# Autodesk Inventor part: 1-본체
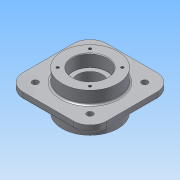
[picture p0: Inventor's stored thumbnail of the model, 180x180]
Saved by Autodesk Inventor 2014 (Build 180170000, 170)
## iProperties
Created: 2015-09
Part Number: 1-본체
Material: 알루미늄 6061
Document SubType Name: Modeling
Designer: study
Density: 2.71 g/cm^3
Appearance: 알루미늄 - 평지
Mass: 1464.68 g
Surface Area: 800.934 cm^2
Volume: 540.471 cm^3
Author: study
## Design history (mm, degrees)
sketch "스케치1"
  geometry: L1 (-75, 75)-(75, 75); L2 (75, 75)-(75, -75); L3 (75, -75)-(-75, -75); L4 (-75, -75)-(-75, 75); L5 (-75, 75)-(75, -75); L6 (75, 75)-(-75, -75); 1 further point
  constraints: 12 end point, 2 midpoint, 2 parallel, 1 horizontal, 1 perpendicular
  dimensions: "d0" = 150 distance of L1.start L1.end; "d1" = 150 distance of L3.end L1.start
extrude "돌출1" new body sketch "스케치1" distance "d2" = 12; taper "d3" = 0 deg
sketch "스케치2"
  geometry: C1 r 50 at (0, 0); 1 further point
  constraints: 1 centre point, 1 coincident
  dimensions: "d5" = 100 diameter of C1
extrude "돌출2" join sketch "스케치2" distance "d6" = 23; taper "d7" = 0 deg
sketch "스케치3"
  geometry: C1 r 50 at (0, 0); 1 further point
  constraints: 1 centre point, 1 coincident
  dimensions: "d8" = 100 diameter of C1
extrude "돌출3" join sketch "스케치3" distance "d9" = 35; taper "d10" = 0 deg
sketch "스케치4"
  geometry: C1 r 50 at (0, 0) reference
hole "구멍1" sketch "스케치4" at (0, 0) diameter "d16" = 45; stored, may be unused: countersink angle "d20" = 90 deg, drill point angle "d22" = 118 deg; dims "d17" = 6, "d18" = 62, "d19" = 22, "d21" = 8
hole "구멍2" diameter "d25" = 45; stored, may be unused: countersink angle "d29" = 90 deg, drill point angle "d31" = 118 deg; dims "d23" = 10, "d24" = 10, "d26" = 6, "d27" = 62, "d28" = 22, "d30" = 8
sketch "스케치7"
  geometry: C1 r 31 at (0, 0) reference; C2 r 50 at (0, 0) reference; A1 r 41 centre (0, 0) between (-28.991, 28.991) and (28.991, 28.991); 2 further points
  constraints: 4 point on circle, 2 vertical alignment, 1 centre point, 1 coincident, 1 horizontal alignment
  dimensions: "d51" = 82 diameter of A1; "d53" = 90 deg dimension on C1.centre A1.start A1.end
hole "구멍5" sketch "스케치7" at (-28.991, 28.991), (28.991, 28.991), (-28.991, -28.991), (28.991, -28.991) diameter "d54" = 4.917; stored, may be unused: countersink angle "d58" = 90 deg, drill point angle "d60" = 118 deg; dims "d55" = 10, "d56" = 62, "d57" = 22, "d59" = 13
sketch "스케치9"
  geometry: C1 r 50 at (0, 0) reference; C2 r 10 at (-49, 49); C3 r 10 at (49, 49); C4 r 10 at (-49, -49); C5 r 10 at (49, -49)
  constraints: 4 centre point, 2 horizontal alignment, 1 equal radius
  dimensions: "d62" = 20 diameter of C2; "d63" = 49 horizontal distance of C1.centre C2.centre; "d64" = 98 distance of C3.centre C2.centre; "d65" = 20 diameter of C5; "d66" = 20 diameter of C4; "d67" = 49 horizontal distance of C1.centre C4.centre; "d68" = 98 distance of C5.centre C4.centre; "d69" = 49 horizontal distance of C1.centre C2.centre; "d70" = 98 distance of C4.centre C2.centre
extrude "돌출5" join sketch "스케치9" distance "d71" = 5; taper "d72" = 0 deg
sketch "스케치10"
  geometry: C1 r 10 at (0, 0) reference; 1 further point
sketch "스케치11"
  geometry: L1 (75, 75)-(-75, 75) reference; L2 (-75, 75)-(-75, -75) reference; L3 (-75, -75)-(75, -75) reference; L4 (75, -75)-(75, 75) reference; C1 r 10 at (-49, -49) reference; C2 r 10 at (-49, 49) reference; C3 r 10 at (49, 49) reference; C4 r 10 at (49, -49) reference; C5 r 50 at (0, 0) reference
hole "구멍7" sketch "스케치10" diameter "d80" = 11; stored, may be unused: countersink angle "d84" = 90 deg, drill point angle "d86" = 0 deg; dims "d81" = 10, "d82" = 62, "d83" = 22, "d85" = 13
sketch "스케치12"
  geometry: C1 r 10 at (0, 0) reference; 1 further point
hole "구멍8" sketch "스케치12" at (0, 0) diameter "d87" = 11; stored, may be unused: countersink angle "d91" = 90 deg, drill point angle "d93" = 0 deg; dims "d88" = 10, "d89" = 62, "d90" = 22, "d92" = 13
sketch "스케치13"
  geometry: C1 r 10 at (0, 0) reference; 1 further point
hole "구멍9" sketch "스케치13" at (0, 0) diameter "d94" = 11; stored, may be unused: countersink angle "d98" = 90 deg, drill point angle "d100" = 0 deg; dims "d95" = 10, "d96" = 62, "d97" = 22, "d99" = 13
sketch "스케치14"
  geometry: C1 r 10 at (0, 0) reference; 1 further point
hole "구멍10" sketch "스케치14" at (0, 0) diameter "d101" = 11; stored, may be unused: countersink angle "d105" = 90 deg, drill point angle "d107" = 0 deg; dims "d102" = 10, "d103" = 62, "d104" = 22, "d106" = 13
fillet "모깎기2" dims "d108" = 30
fillet "모깎기3" dims "d109" = 3, "d110" = 0.3
chamfer "모따기1" distance "d111" = 1; stored, may be unused: second distance "d112" = 2, angle "d113" = 45 deg
fillet "모깎기4" dims "d114" = 3
sketch "스케치16"
  geometry: C1 r 53 at (0, 0) reference; 1 further point
  constraints: 1 vertical alignment, 1 other
  dimensions: "d115" = 65 distance of C1.centre point (0, 65)
feature "엠보싱1" sketch "스케치16" dims "d0" = 150, "d1" = 150, "d116" = 1, "d117" = 0
node "솔리드1"
mirror "대칭2"
